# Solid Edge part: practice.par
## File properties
Author: edge
Template: Normal.par
Last saved by: edge
Revision: 26
Application: Solid Edge
文書内容のタイプ: 0
Accuracy: 0.990
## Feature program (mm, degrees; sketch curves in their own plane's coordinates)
sketch for "ExtrudedProtrusion_2" plane through (0, 0, 25) normal (0, 0, 1) x-axis (1, 0, 0)
  line (-165, -40) -> (50, -40)
  line (50, -40) -> (50, 40)
  line (50, 40) -> (-165, 40)
  line (-165, 40) -> (-165, -40)
  dimension (linear) = 50
  dimension (linear) = 165
extrude "ExtrudedProtrusion_2" add finite 60 along +normal  FiniteDepth2 = 50 mm
sketch for "unnamed Cutout 1" plane through (0, 0, 0) normal (0, -1, 0) x-axis (1, 0, 0)
  line (65, 105) -> (-150, 105)
  line (-150, 105) -> (-150, 25)
  line (-150, 25) -> (65, 25)
  line (65, 25) -> (65, 105)
extrude "unnamed Cutout 1" cut through
sketch for "unnamed Cutout 2" plane through (0, 0, 0) normal (0, -1, 0) x-axis (1, 0, 0)
  line (-50, 10) -> (-185, 10)
  line (-185, 10) -> (-185, -80)
  line (-185, -80) -> (-50, -80)
  line (-50, -80) -> (-50, 10)
  dimension (linear) = 185
  dimension (linear) = 185
extrude "unnamed Cutout 2" cut through
sketch for "unnamed Cutout 3" plane through (-50, 0, 25) normal (0, 0, 1) x-axis (1, 0, 0)
  line (-47.5, 12.5) -> (-47.5, -12.5)
  line (-32.5, 12.5) -> (-32.5, -12.5)
extrude "unnamed Cutout 3" cut through along -normal
pattern "unnamed Pattern 1" of "unnamed Cutout 3"
sketch for "Hole_1" plane through (-50, 0, 25) normal (0, 0, 1) x-axis (1, 0, 0)
  hole centre (70, 0) bore radius 3.3235
hole "Hole_1" nominal diameter 8 finite  ThreadDepth = 12 mm; VBottomAngle = 118 deg
sketch for "unnamed Hole 1" plane through (-50, 0, 25) normal (0, 0, 1) x-axis (1, 0, 0)
  hole centre (30, 0) bore radius 3.3235
hole "unnamed Hole 1" finite
sketch for "Hole_3" plane through (0, 0, 0) normal (0, -1, 0) x-axis (1, 0, 0)
  hole centre (25, 0) bore radius 7.647
hole "Hole_3" nominal diameter 18 through
sketch for "unnamed Hole 2" plane through (0, 0, 0) normal (0, -1, 0) x-axis (1, 0, 0)
  hole centre (-25, 0) bore radius 7.647
hole "unnamed Hole 2" through
sketch for "Hole_5" plane through (-150, 0, 55) normal (1, 0, 0) x-axis (0, 1, 0)
  hole centre (0, 0) bore radius 10
hole "Hole_5" diameter 20 through
sketch for "Hole_6" plane through (-150, 0, 55) normal (1, 0, 0) x-axis (0, 1, 0)
  hole centre (30, 20) bore radius 5
hole "Hole_6" diameter 10 through
sketch for "unnamed Hole 3" plane through (-150, 0, 55) normal (1, 0, 0) x-axis (0, 1, 0)
  hole centre (-30, -20) bore radius 5
hole "unnamed Hole 3" through
sketch for "unnamed Hole 4" plane through (-150, 0, 55) normal (1, 0, 0) x-axis (0, 1, 0)
  hole centre (30, -20) bore radius 5
hole "unnamed Hole 4" through
sketch for "unnamed Hole 5" plane through (-150, 0, 55) normal (1, 0, 0) x-axis (0, 1, 0)
  hole centre (-30, 20) bore radius 5
  dimension (linear) = 30
hole "unnamed Hole 5" through
pattern "unnamed Pattern 2" of "Hole_6", "unnamed Hole 3", "unnamed Hole 4", "unnamed Hole 5"
chamfer "Chamfer_1" setback 3
chamfer "Chamfer_2" setback 10  SetBackValue2 = 30 deg
pattern "unnamed Pattern 3"
pattern "unnamed Pattern 4" of "Hole_1", "unnamed Hole 1"
pattern "unnamed Pattern 5" of "Hole_3", "unnamed Hole 2"
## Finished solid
Body 1: solid body, 31 faces, 72 edges, 36 vertices.
  Faces by surface: plane 16, cylinder 13, cone 2
  Edges by curve: line 46, circle 26
Bounding box of the edges (mm): 215.000 x 80.000 x 110.000, from (-165, -40, -25) to (50, 40, 85).
Cylindrical faces by radius (mm): R3.3235 x2, R5 x4, R7.5 x4, R7.647 x2, R10 x1
Conical faces (half-angle, radius in mm at the cone's reference point): 59 deg R3.3235 x2
Planar faces by outward normal: +x 4, +y 1, +z 2, -x 4, -y 1, -z 2, oblique 2
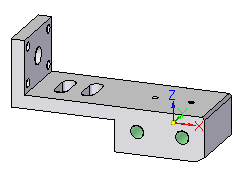
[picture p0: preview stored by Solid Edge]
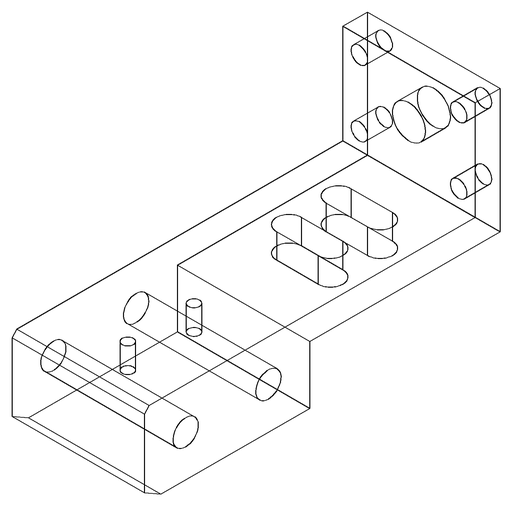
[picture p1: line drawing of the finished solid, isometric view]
